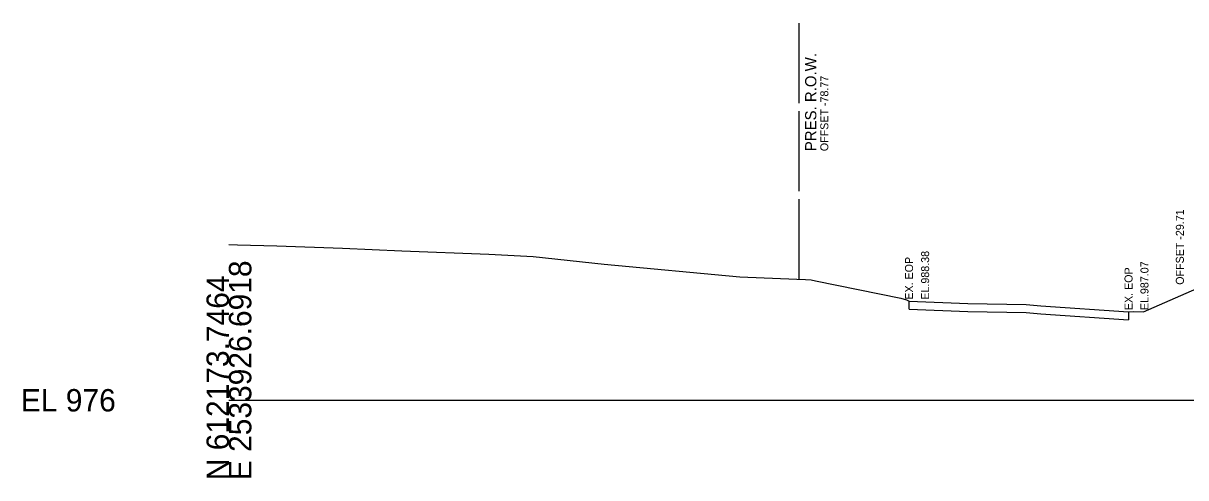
# Model space of a CAD drawing. Extents: x -120 to 2876, y -25 to 8560.
# Drawn here: x -25.7 to 119.5, y 6990.3 to 7047.2 of the extents above; entities that cross this region are included whole.
import ezdxf

# ---------------------------------------------------------------- set-up
doc = ezdxf.new("R2010")
doc.units = 0
for name, color, linetype in [('DESIGN - SHEET - Light Grid', 7, 'Continuous'), ('DESIGN - TYPICAL - Slope Tie Text', 7, 'Continuous'), ('SURVEY - GROUND - Existing Pavement Layer', 7, 'Continuous'), ('SURVEY - GROUND - Existing Pavement Text', 7, 'Continuous'), ('SURVEY - GROUND - Top of Ground', 7, 'Continuous'), ('SURVEY - PROPERTY - ROW Lines', 7, 'Continuous'), ('SURVEY - PROPERTY - ROW Lines Text', 7, 'Continuous')]:
    doc.layers.add(name, color=color, linetype=linetype)

msp = doc.modelspace()

# ---------------------------------------------------------------- linework, layer by layer
at = {"layer": 'DESIGN - SHEET - Light Grid'}
msp.add_line((0, 7000), (150, 7000), dxfattribs=at)
at = {"layer": 'SURVEY - GROUND - Existing Pavement Layer'}
for p, q in [((84.96, 7011.38), (84.96, 7012.38)), ((84.96, 7011.38), (92.29, 7011.12)), ((92.29, 7011.12), (99.6, 7010.96)), ((99.6, 7010.96), (101.43, 7010.83)), ((101.43, 7010.83), (112.38, 7010.07)), ((112.38, 7011.07), (112.38, 7010.07))]:
    msp.add_line(p, q, dxfattribs=at)
at = {"layer": 'SURVEY - GROUND - Top of Ground'}
msp.add_line((1.07, 7019.45), (5.99, 7019.3), dxfattribs=at)
for points in [[(0, 7019.49), (1.07, 7019.45)], [(5.99, 7019.3), (14.18, 7019.03), (21.62, 7018.67), (32.48, 7018.27), (38, 7017.99), (46.86, 7017.03), (63.81, 7015.42), (70.94, 7015.16), (72.01, 7015.12), (72.74, 7015.07), (73.27, 7014.93), (83.92, 7012.78), (84.66, 7012.55), (84.96, 7012.38), (92.29, 7012.12), (99.6, 7011.96), (101.43, 7011.83), (112.38, 7011.07), (112.99, 7011.11), (114.27, 7011.04), (123.56, 7015.13)]]:
    msp.add_lwpolyline(points, dxfattribs=at)
at = {"layer": 'SURVEY - PROPERTY - ROW Lines'}
for p, q in [((71.23, 7037.15), (71.23, 7047.15)), ((71.23, 7026.15), (71.23, 7036.15)), ((71.23, 7015.15), (71.23, 7025.15))]:
    msp.add_line(p, q, dxfattribs=at)

# ---------------------------------------------------------------- texts
at = {"layer": 'DESIGN - SHEET - Light Grid'}
for s, p in [('E 2533926.6918', (2.8, 6990)), ('N 612173.7464', (0, 6990))]:
    msp.add_text(s, height=2.8, rotation=90, dxfattribs=at).set_placement(p)
msp.add_text('EL 976', height=2.8, dxfattribs=at).set_placement((-26, 6998.6))
at = {"layer": 'DESIGN - TYPICAL - Slope Tie Text'}
msp.add_text('OFFSET -29.71', height=1, rotation=90, dxfattribs=at).set_placement((119.29, 7014.44))
at = {"layer": 'SURVEY - GROUND - Existing Pavement Text'}
for s, p in [('EL.988.38', (87.47, 7012.58)), ('EX. EOP', (85.46, 7012.58)), ('EL.987.07', (114.87, 7011.27)), ('EX. EOP', (112.88, 7011.27))]:
    msp.add_text(s, height=1, rotation=90, dxfattribs=at).set_placement(p)
at = {"layer": 'SURVEY - PROPERTY - ROW Lines Text'}
for s, height, p in [('PRES. R.O.W.', 1.4, (73.38, 7031.15)), ('OFFSET -78.77', 1, (74.88, 7031.15))]:
    msp.add_text(s, height=height, rotation=90, dxfattribs=at).set_placement(p)

doc.saveas('drawing.dxf')
